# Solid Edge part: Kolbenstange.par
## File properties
Author: bmolnar
Last saved by: bmolnar
Revision: 78
Sűrűség: 0,000 kg/m^3
Pontosság: 0,990
Username: bmolnar
Dokumentum tartalom típus: 0
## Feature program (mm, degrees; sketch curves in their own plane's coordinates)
base feature "unnamed BaseFeature 1"
sketch for "unnamed Protrusion 1" plane through (42.5, 0, 0) normal (1, 0, 0) x-axis (0, 0, -1)
  circle centre (0, 0) radius 31.5
extrude "unnamed Protrusion 1" add finite 17.85 along +normal
sketch for "Kihúzás_4" #1 plane through (42.5, 0, 0) normal (1, 0, 0) x-axis (0, 0, -1)
  circle centre (0, 0) radius 8
sketch for "Kihúzás_4" #2 plane through (42.5, 0, 0) normal (1, 0, 0) x-axis (0, 0, -1)
  circle centre (0, 0) radius 31.5
extrude "Kihúzás_4" add finite 10.85 along -normal
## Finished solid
Body 1: solid body, 14 faces, 20 edges, 8 vertices.
  Faces by surface: plane 8, cylinder 4, cone 1, torus 1
  Edges by curve: circle 10, line 6, curve on surface 2, ellipse 2
Bounding box of the edges (mm; curved faces can reach further): 65.350 x 63.000 x 63.000, from (-5, -31.5, -31.5) to (60.35, 31.5, 31.5).
Cylindrical faces by radius (mm): R3.3235 x1, R4.125 x1, R8 x1, R31.5 x1
Conical faces (half-angle, radius in mm at the cone's reference point): 59 deg R1.6618 x1
Toroidal faces (ring radius, tube radius in mm): R6.2 r1.8 x1
Planar faces by outward normal: +x 1, +y 1, -x 3, -y 1, oblique 2
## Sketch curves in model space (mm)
circle centre (42.5, 0, 0) radius 31.5
circle centre (42.5, 0, 0) radius 8
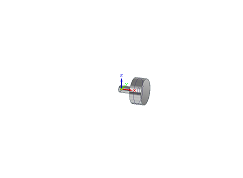
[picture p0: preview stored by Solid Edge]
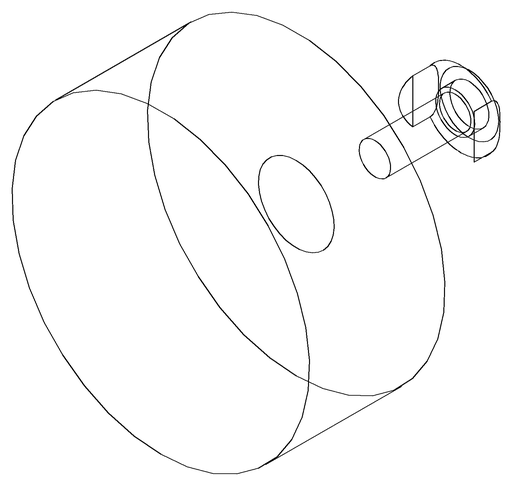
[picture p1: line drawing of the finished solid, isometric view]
